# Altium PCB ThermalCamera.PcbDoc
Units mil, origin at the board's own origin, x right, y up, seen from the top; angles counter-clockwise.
Board outline 2150 x 2960 mil, 2 copper layers (Top Layer, Bottom Layer), stack 64.8 mil thick; 71 components, 50 nets, 249 pads, 73 vias.
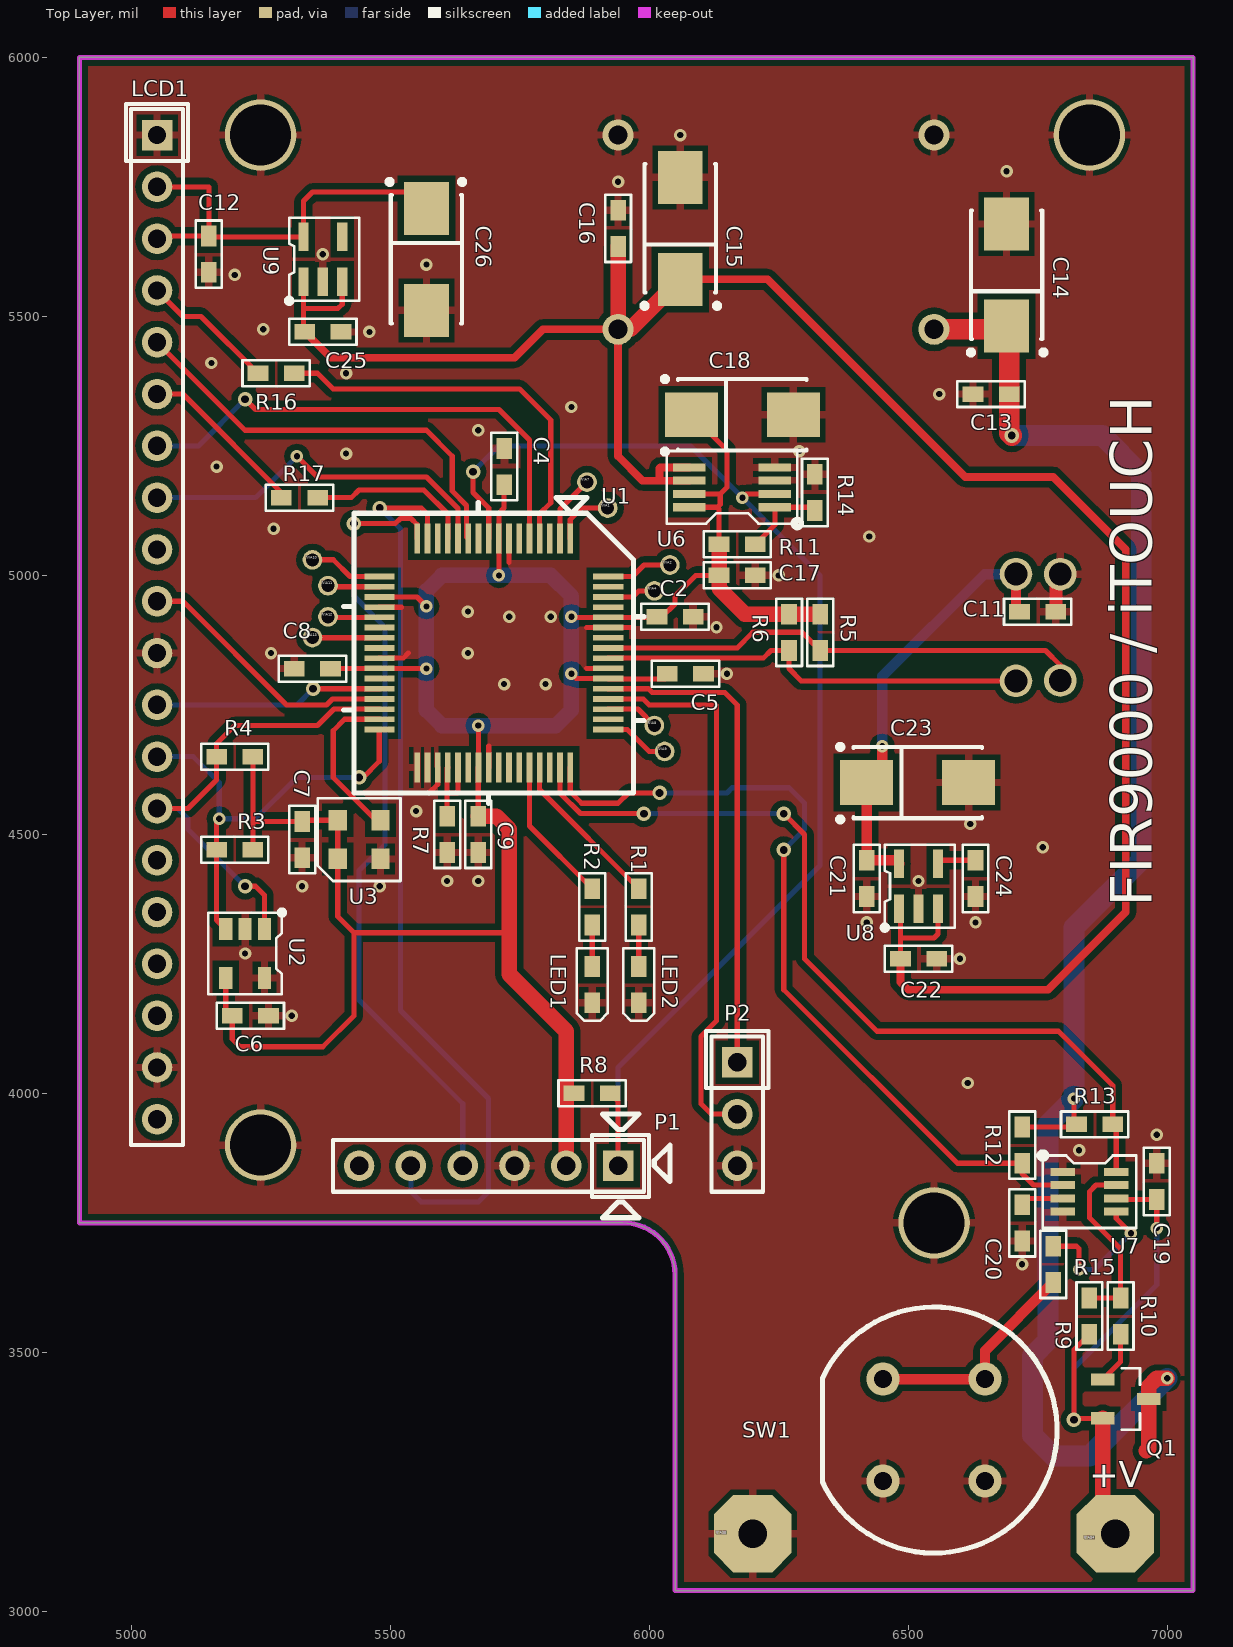
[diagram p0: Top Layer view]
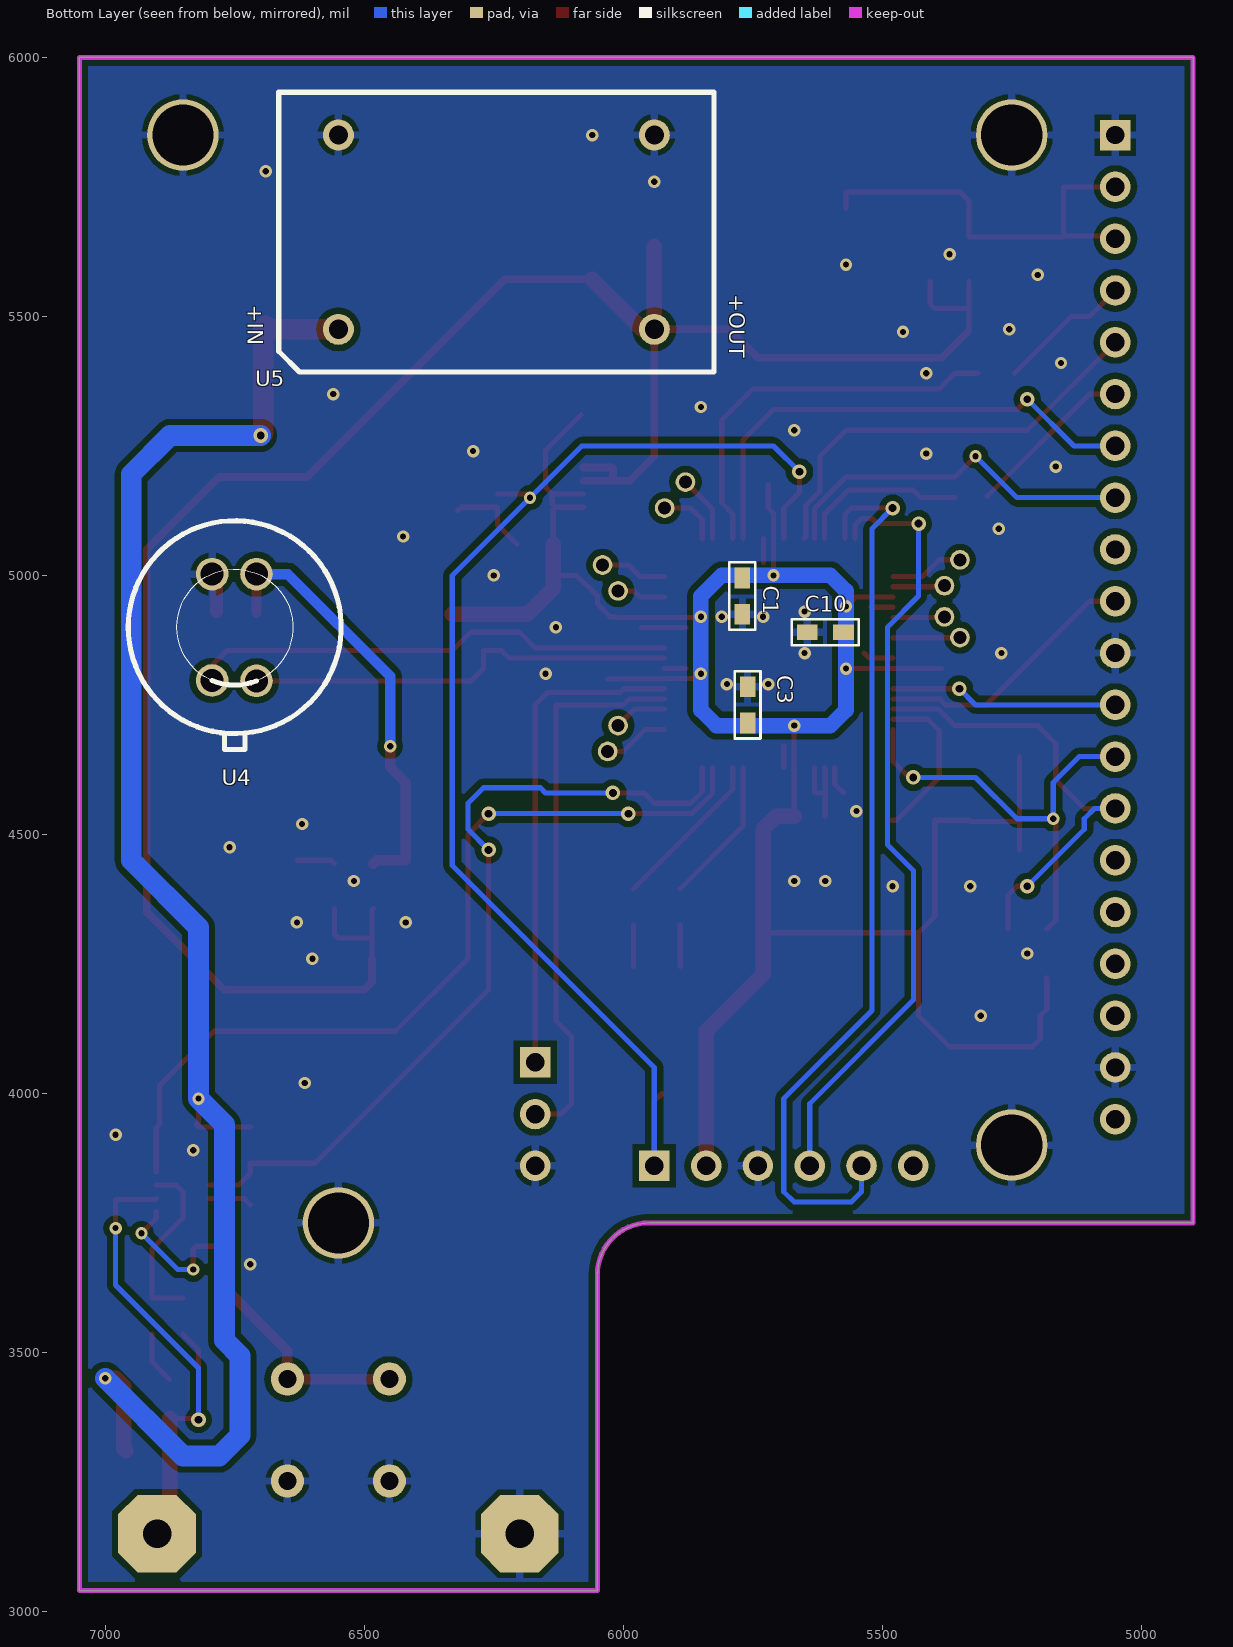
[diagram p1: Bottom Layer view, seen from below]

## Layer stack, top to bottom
Top Solder: solder mask 0.4, Solder Resist, Dk 3.5
Top Layer: signal copper 1.4
Dielectric1: core 62, FR-4, Dk 4.8
Bottom Layer: signal copper 1.4
Bottom Solder: solder mask 0.4, Solder Resist, Dk 3.5

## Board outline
4900,3750 5950,3750 cw(c5950,3650) 6050,3650 6050,3040 7050,3040 7050,6000 4900,6000

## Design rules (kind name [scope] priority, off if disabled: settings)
Clearance "PAD Keepout" [(InPadClass('All Pads')) vs (InPoly)] p1: gap=12 ignorepadtopadclearanceinfootprint=FALSE except(0: Arc-Hole Track-Hole SMDPad-Hole THPad-Hole Via-Hole Fill-Hole Poly-Hole Region-Hole Text-Hole) // 7 Mil Keepout
Clearance "GND Planes" [(inPoly)] p2: gap=12 ignorepadtopadclearanceinfootprint=FALSE except(0: Arc-Hole Track-Hole SMDPad-Hole THPad-Hole Via-Hole Fill-Hole Poly-Hole Region-Hole Text-Hole) // 12 mil Clearence
Clearance [All] p3: gap=6 ignorepadtopadclearanceinfootprint=FALSE except(0: Arc-Hole Track-Hole SMDPad-Hole THPad-Hole Via-Hole Fill-Hole Poly-Hole Region-Hole Text-Hole)
ComponentClearance [All] p1: gap=-1 collisioncheckmode=3 verticalgap=-1 showdistances=FALSE
FanoutControl Fanout_Default [All] p1: bgadir=Out bgaviamode=Centered fanoutstyle=Auto fanoutdirection=OutOnly viagrid=1 // Fanout_Default (Default Rule)
Height [All] p1: minheight=-1 maxheight=1000 prefheight=500
HoleSize [All] p1: absolutevalues=TRUE maxlimit=250 minlimit=8 maxpercent=80.000 minpercent=20.000
HoleToHoleClearance [All] p1: gap=12 allowstackedmicrovias=FALSE
MinimumAnnularRing [All] p1: minimumring=6
MinimumSolderMaskSliver [All] p1: minsoldermaskwidth=1
PlaneClearance [All] p1: clearance=12
PlaneConnect [All] p1: planeconnectstyle=Relief reliefexpansion=12 reliefentries=4 reliefconductorwidth=10 reliefairgap=10
PolygonConnect PolygonConnect_Gnd_Vias [InNet('GND') AND IsVia] p1: connectstyle=Direct reliefconductorwidth=10 reliefentries=4 polygonreliefangle="90 Angle" airgapwidth=10
PolygonConnect PolygonConnect_MTG_Holes [InNet('GND') AND IsVia AND (AsMils(PadXSize_AllLayers) = 250.0)] p2: connectstyle=Direct reliefconductorwidth=10 reliefentries=4 polygonreliefangle="90 Angle" airgapwidth=10
PolygonConnect PolygonConnect_Deafult [All] p3: connectstyle=Relief reliefconductorwidth=15 reliefentries=4 polygonreliefangle="90 Angle" airgapwidth=10
RoutingCorners [All] p1: cornerstyle=45-Degree minsetback=50 maxsetback=100
RoutingVias [All] p1: holewidth=10 width=23 viastyle="Through Hole" minholewidth=8 minwidth=20 maxholewidth=250 maxwidth=300
SilkToSilkClearance [All] p1: silktosilkclearance=0
SilkToSolderMaskClearance SilkscreenOverComponentPads [IsPad] p1: minsilkscreentomaskgap=-1 clearancetoexposedcopper=TRUE
SolderMaskExpansion SolderMaskExpansion_VIAS [IsVia] p1: expansion=-3 istentingtop=FALSE
SolderMaskExpansion SolderMaskExpansion_PADS [IsPad] p2: expansion=3 istentingtop=FALSE
SolderMaskExpansion [All] p3: expansion=3 istentingtop=FALSE
Width [All] p1: maxlimit=200 minlimit=6 preferedwidth=10 minimp=50.000000 maximp=50.000000 favimp=50.000000
15 further rules are at their usual default settings.

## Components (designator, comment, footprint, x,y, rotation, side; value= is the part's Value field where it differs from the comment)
C1 "C603-0.22u" 0603 5770,4960 r270 bottom
C2 "C603-0.01u" 0603 6050,4920 r0 top
C3 "C603-0.22u" 0603 5760,4750 r270 bottom
C4 "C603-0.01u" 0603 5720,5210 r270 top
C5 "C603-0.01u" 0603 6070,4810 r180 top
C6 "C603-0.22u" 0603 5230,4150 r180 top
C7 "C603-0.22u" 0603 5330,4490 r90 top
C8 "C603-0.01u" 0603 5350,4820 r0 top
C9 "C603-0.01u" 0603 5670,4500 r90 top
C10 "C603-0.22u" 0603 5610,4890 r180 bottom
C11 "C603-0.01u" 0603 6750,4930 r0 top
C12 "C603-0.22u" 0603 5150,5620 r90 top
C13 "C603-0.22u" 0603 6660,5350 r180 top
C14 "CT-220u-10V" 6032-28 6690,5580 r90 top
C15 "CT-220u-10V" 6032-28 6060,5670 r90 top
C16 "C603-0.22u" 0603 5940,5670 r90 top
C17 "C603-0.22u" 0603 6170,5000 r0 top
C18 "CT-220u-10V" 6032-28 6180,5310 r0 top
C19 "C603-0.22u" 0603 6980,3830 r90 top
C20 "C603-0.47u" 0603 6720,3750 r270 top
C21 "C603-0.22u" 0603 6420,4415 r270 top
C22 "C603-0.22u" 0603 6520,4260 r0 top
C23 "CT-220u-10V" 6032-28 6518.43,4600 r0 top
C24 "C603-0.22u" 0603 6630,4415 r270 top
C25 "C603-0.22u" 0603 5370,5470 r0 top
C26 "CT-220u-10V" 6032-28 5570,5610 r270 top
LCD1 "Adafruit 2.8\" TFT SPI" Header_SIL_20 5050,5850 r270 top
LED1 "LED603-YEL" 0603LED-YEL 5890,4210 r270 top
LED2 "LED603-YEL" 0603LED-YEL 5980,4210 r270 top
P1 "SIL-6" ProgHeader_SIL 5940,3860 r180 top
P2 "SIL-3" Header_SIL_3 6170,4060 r270 top
Q1 "FDV304P" SOT23 6920,3410 r0 top
R1 "R603-316" 0603 5980,4360 r270 top
R2 "R603-316" 0603 5890,4360 r270 top
R3 "R603-5.11k" 0603 5200,4470 r180 top
R4 "R603-5.11k" 0603 5200,4650 r180 top
R5 "R603-1.54k" 0603 6330,4890 r270 top
R6 "R603-1.54k" 0603 6270,4890 r270 top
R7 "R603-5.11k" 0603 5610,4500 r270 top
R8 "R603-10k" 0603 5890,4000 r0 top
R9 "R603-100k" 0603 6850,3570 r90 top
R10 "R603-100k" 0603 6910,3570 r90 top
R11 "R603-53.6k" 0603 6170,5060 r0 top
R12 "R603-100k" 0603 6720,3900 r270 top
R13 "R603-100k" 0603 6860,3940 r0 top
R14 "R603-30.1k" 0603 6320,5160 r90 top
R15 "R603-1k" 0603 6780,3670 r90 top
R16 "R603-24.9" 0603 5280,5390 r0 top
R17 "R603-24.9" 0603 5325,5150 r0 top
SW1 "D6R40 F1 LFS" D6R40_F1_LFS 6550,3350 r0 top
U1 "PIC32MZ2048EFH064-250I/PT" TQFP64_10x10MC 5700,4850 r270 top
U2 "24LC64FT-I/OT" SOT23_5 5220,4270 r270 top
U3 "DSC6003CI2A-024.0000T" MICREL-3.2x2.5MM-OSC 5440,4490 r90 top
U4 "MLX90640" MLX90640 6750,4900 r180 bottom
U5 "EBAY_MODULE" BUCK_MODULE 6245,5662.5 r0 bottom
U6 "TPS77301DGK" DGK8 6160,5170 r180 top
U7 "LTC2955TS8-2" SOT23_8 6850,3810 r0 top
U8 "LP2985A-3.3DBV" DBV 6520,4400 r90 top
U9 "LP2985A-3.3DBV" DBV 5370,5610 r90 top
VIA1 "VIA038_025" VIA038_25 5920,5130 r90 top
VIA2 "VIA038_025" VIA038_25 6040,5020 r90 top
VIA4 "VIA038_025" VIA038_25 6010,4970 r90 top
VIA7 "VIA038_025" VIA038_25 5880,5180 r90 top
VIA8 "VIA038_025" VIA038_25 6010,4710 r90 top
VIA9 "VIA038_025" VIA038_25 6030,4660 r90 top
VIA10 "VIA038_025" VIA038_25 5350,5030 r90 top
VIA11 "VIA038_025" VIA038_25 5380,4980 r90 top
VIA12 "VIA038_025" VIA038_25 5380,4920 r90 top
VIA13 "VIA038_025" VIA038_25 5350,4880 r90 top
VIA14 "VIA150_055" VIA150_055 6900,3150 r90 top
VIA15 "VIA150_055" VIA150_055 6200,3150 r90 top

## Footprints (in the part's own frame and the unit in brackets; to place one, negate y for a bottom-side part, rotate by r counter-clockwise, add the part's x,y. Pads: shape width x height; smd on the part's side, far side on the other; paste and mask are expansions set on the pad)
0603 [mil] "0603 Normal Pads"
  rect 40x30 smd: 1(-35,0) 2(35,0)
  silkscreen extent -65,-25 65,25, body extent -36,-16 36,16, height 38
0603LED-YEL [mil] "0603 LED YELLOW"
  rect 40x30 smd: 1(35,0) 2(-35,0)
  silkscreen extent -70,-30 70,30, body extent -35,-15 35,15, height 31
6032-28 [mm] "Tantalum C"
  rect 2.6x2.2 smd: 1(-2.5,0) 2(2.5,0)
  silkscreen extent -3.92,-1.93 3.15,1.87, body extent -2.57,-1.4 2.57,1.4, height 2.49
BUCK_MODULE [mil] "EBAY BUCK CONVERTER MODULE"
  round 60 hole 37: 1(305,187.5) 2(305,-187.5) 3(-305,-187.5) 4(-305,187.5)
  silkscreen extent -420,-270 420,270, body extent -400,-250 400,250, height 200
D6R40_F1_LFS [mil] "TH PUSH BUTTON TACTILE VERT"
  round 64 hole 35: 1(-98.43,98.43) 2(-98.43,-98.43) 3(98.43,-98.43) 4(98.43,98.43)
  silkscreen extent -215,-238 237,238, body extent -234,-236 236,236, height 571
DBV [mil] "TI DBV FOOTPRINT (SOT-23-5)"
  rect 55.1x19.7 smd: 1(-43.3,37.4) 2(-43.3,0) 3(-43.3,-37.4) 4(43.3,-37.4) 5(43.3,37.4)
  silkscreen extent -85,-70 80,70, body extent -56,-58 56,57, height 42
DGK8 [mil] "MSOP8 (TI)"
  rect 63x15.7 smd: 1(-82.7,38.4) 2(-82.7,12.8) 3(-82.7,-12.8) 4(-82.7,-38.4) 5(82.7,-38.4) 6(82.7,-12.8) 7(82.7,12.8) 8(82.7,38.4)
  silkscreen extent -134,-70 126,78, body extent -96,-59 97,59, height 38
Header_SIL_3 [mm] "3 Pin Header (SIL)"
  rect 1.5x1.5 hole 0.9: 1(0,0)
  round 1.5 hole 0.9: 2(2.54,0) 3(5.08,0)
  silkscreen extent -1.52,-1.52 6.35,1.52, body extent -1.27,-1.27 6.35,1.27, height 5.79
Header_SIL_20 [mm] "20 Pin Header (SIL)"
  rect 1.5x1.5 hole 0.9: 1(0,0)
  round 1.5 hole 0.9: 2(2.54,0) 3(5.08,0) 4(7.62,0) 5(10.16,0) 6(12.7,0) 7(15.24,0) 8(17.78,0) 9(20.32,0) 10(22.86,0) 11(25.4,0) 12(27.94,0) 13(30.48,0) 14(33.02,0) 15(35.56,0) 16(38.1,0) 17(40.64,0) 18(43.18,0) 19(45.72,0) 20(48.26,0)
  silkscreen extent -1.52,-1.52 49.53,1.52, body extent -1.27,-1.27 49.53,1.28, height 5.79
MICREL-3.2x2.5MM-OSC [mm] "MICREL 3.2X2.5MM A PKG OSCILATOR"
  rect 1x0.9 smd: 1(-0.95,1.05) 2(-0.95,-1.05) 3(0.95,-1.05) 4(0.95,1.05)
  silkscreen extent -2.03,-2.03 2.03,2.03, body extent -1.26,-1.61 1.26,1.61, height 0.91
MLX90640 [mm] "IR SENSOR"
  round 1.6 hole 1.12: 1(-1.11,-2.614) 2(1.064,-2.633) 3(1.064,2.6) 4(-1.11,2.6)
  silkscreen extent -5.22,-6 5.22,5.22, body extent -4.61,-5.25 4.65,4.64, height 11.35
ProgHeader_SIL [mm] "6 Pin Programming Header (SIL)"
  rect 1.5x1.5 hole 0.9: 1(0,0)
  round 1.5 hole 0.9: 2(2.54,0) 3(5.08,0) 4(7.62,0) 5(10.16,0) 6(12.7,0)
  silkscreen extent -2.54,-2.54 13.97,2.54, body extent -1.27,-1.27 13.97,1.28, height 5.79
SOT23 [mm] "SOT23, 123 Normal Pinout"
  rect 1.15x0.6 smd: 1(-1.125,0.95) 2(1.125,0) 3(-1.125,-0.95)
  silkscreen extent -0.2,-1.5 0.7,1.5, body extent -1.26,-1.46 1.26,1.46, height 0.97
SOT23_5 [mm] "SOT23, 5 Lead Normal Pinout"
  rect 1.1x0.65 smd: 1(-1.2,0.95) 2(-1.2,0) 3(-1.2,-0.95) 4(1.2,-0.95) 5(1.2,0.95)
  silkscreen extent -2.13,-1.8 2,1.93, body extent -1.42,-1.46 1.42,1.46, height 1.07
SOT23_8 [mil] "TSOT23-8 From LTC6910 Data Sheet"
  rect 48x15.7 smd: 1(-51.6,38.4) 2(-51.6,12.8) 3(-51.6,-12.8) 4(-51.6,-38.4) 5(51.6,-38.4) 6(51.6,-12.8) 7(51.6,12.8) 8(51.6,38.4)
  silkscreen extent -97,-70 90,77, body extent -55,-57 55,57, height 39
TQFP64_10x10MC [mil] "TQFP64 10x10x1.6mm 0.5mm grid"
  rect 58x11 smd: 1(-221,147.64) 2(-221,127.95) 3(-221,108.27) 4(-221,88.58) 5(-221,68.9) 6(-221,49.21) 7(-221,29.53) 8(-221,9.84) 9(-221,-9.84) 10(-221,-29.53) 11(-221,-49.21) 12(-221,-68.9) 13(-221,-88.58) 14(-221,-108.27) 15(-221,-127.95) 16(-221,-147.64) 33(221,-147.64) 34(221,-127.95) 35(221,-108.27) 36(221,-88.58) 37(221,-68.9) 38(221,-49.21) 39(221,-29.53) 40(221,-9.84) 41(221,9.84) 42(221,29.53) 43(221,49.21) 44(221,68.9) 45(221,88.58) 46(221,108.27) 47(221,127.95) 48(221,147.64)
  rect 11x58 smd: 17(-147.64,-221) 18(-127.95,-221) 19(-108.27,-221) 20(-88.58,-221) 21(-68.9,-221) 22(-49.21,-221) 23(-29.53,-221) 24(-9.84,-221) 25(9.84,-221) 26(29.53,-221) 27(49.21,-221) 28(68.9,-221) 29(88.58,-221) 30(108.27,-221) 31(127.95,-221) 32(147.64,-221) 49(147.64,221) 50(127.95,221) 51(108.27,221) 52(88.58,221) 53(68.9,221) 54(49.21,221) 55(29.53,221) 56(9.84,221) 57(-9.84,221) 58(-29.53,221) 59(-49.21,221) 60(-68.9,221) 61(-88.58,221) 62(-108.27,221) 63(-127.95,221) 64(-147.64,221)
  silkscreen extent -300,-290 290,290, body extent -236,-236 236,236, height 47
VIA038_25 [mil] "25/38 Mil PCB Via"
  round 38 hole 25: 1(0,0)
VIA150_055 [mil] "150/55 Mil PCB Via"
  oct 150x150 hole 55: 1(0,0)

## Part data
C1 C2 C3 C4 C5 C6 C7 C8 C9 C10 C11 C12 C13 C16 C17 C19 C20 C21 C22 C24 C25: library part C0603-0.22u, "0.22uF 50V X7R 603 Capacitor"
C14 C15 C18 C23 C26: "220uF/10V Tant"
LCD1: "240x320 TFT LCD"
LED1 LED2: "Yellow LED"
P1: library part "Prog PICKIT Header (SIL)", "PICKIT Programming Header (SIL)"
P2: library part Header_SIL_3, "Header SIL 3 Pin"
Q1: "PMOS 25V, 1.1 Ohm, 460mA"
R1 R2 R3 R4 R5 R6 R7 R8 R9 R10 R11 R12 R13 R14 R15 R16 R17: library part R0603, "0603 Resistor"
SW1: library part PB-PANEL_1, "PB TACTILE THROUGH HOLE"
U1: "PIC32MZ 250 MHz TQFP"
U2: "64K I2C EEPROM"
U3: library part "MEMS 24MHz", "24MHz CLOCK 1.8-3.3V Low Power"
U4: "IR SENSOR 55 DEGREE"
U5: library part EBAY_BUCK_MODULE, "EBAY BUCK MODULE"
U6: "250mA LDO W/Reset Output"
U7: "PushButton Controller"
U8 U9: library part LP2985A, "150mA LDO W/ENABLE"
VIA1 VIA2 VIA4 VIA7 VIA8 VIA9 VIA10 VIA11 VIA12 VIA13: "38/25 Via Only"
VIA14 VIA15: "150 / 55 Via Only"

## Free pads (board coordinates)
  round 138 hole 118: 2(6550,3750) 3(5250,5850) 4(6850,5850) 5(5250,3900)

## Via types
v1: diameter 24, hole 12, Top Layer to Bottom Layer, 60 vias
v2: diameter 28, hole 15, Top Layer to Bottom Layer, 13 vias

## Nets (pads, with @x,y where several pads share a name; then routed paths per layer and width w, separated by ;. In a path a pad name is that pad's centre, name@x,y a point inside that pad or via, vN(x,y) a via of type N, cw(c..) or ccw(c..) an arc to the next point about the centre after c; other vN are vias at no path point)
+3.3V_DIG: C1.1 C2.1 C3.2 C4.2 C5.2 C6.2 C7.2 C8.2 C9.2 C10.2 C17.1 C18.1 P1.2 R3.1 R4.1 R5.1 R6.1 R8.1 R11.1 U1.8 U1.19 U1.26 U1.39 U1.54 U1.60 U2.4 U3.1 U3.4 U6.7 U6.8 | length 5106.6
  Top Layer w10: U2.4 5182.6,4162.4 C6.2 5195,4105 5210,4090 5370,4090 5430,4150 5430,4310 ; R3.1 5235,4525 ; R4.1 5235,4525 ; C8.2 5385.47,4820.47 U1.26 5569.53,4820.47 v1(5570,4820) ; U1.19 5551.73,4958.27 v1(5570,4940) ; C9.2 5670,4628.53 U1.39 5670.47,4709.53 v1(5670,4710) ; v1(5710,5000) 5709.84,5000.16 U1.8 5709.84,5119.84 5720,5130 C4.2 ; 5730,4310 5430,4310 ; v1(5850,4810) 5859.21,4800.79 U1.54 5921.79,4800 C5.2@6030,4800 ; v1(5850,4920) 5851.1,4918.9 U1.60 6013.9,4918.9 C2.1 6025,4920 6050,4945 6050,4960 6090,5000 C17.1 ; U6.8 6131.6,5131.6 ; U6.7 6137.2,5157.2 ; C18.1 6150,5241.57 6150,5170 6137.2,5157.2 ; R11.1 6135,5128.2 6131.6,5131.6 ; 5235,4525 C7.2 5332.4,4527.4 U3.4 U3.1 5398.66,4341.34 5430,4310 ; 6131.6,5131.6 6137.2,5137.2 6137.2,5157.2
  Top Layer w30: C9.2 5705,4535 5730,4510 5730,4310 5730,4230 5840,4120 P1.2 ; R11.1 C17.1 6135,4975 6185,4925 R6.1 R5.1
  Bottom Layer w30: 5570,4740 v1(5570,4820) v1(5570,4940) 5570,4970 5600,5000 v1(5710,5000) 5810,5000 5850,4960 v1(5850,4920) v1(5850,4810) 5850,4740 5820,4710 v1(5670,4710) 5600,4710 5570,4740
+3.3V_LCD: C12.2 C26.1 LCD1.2 LCD1.3 U9.5 | length 825.9
  Top Layer w10: LCD1.3 5055,5655 C12.2 ; LCD1.2 5150,5750 C12.2 ; C26.1 5570,5740 5350,5740 5332.6,5722.6 U9.5 5151.7,5653.3 C12.2
+3.3V_SENSOR: C11.1 C21.1 C23.1 U4.3 U8.5 | length 846.9
  Top Layer w20: v1(6450,4670) 6450,4630 C23.1 C21.1 6475.9,4450 U8.5 ; C11.1@6708.11,4928.11 U4.3
  Bottom Layer w20: v1(6450,4670) 6450,4805 6647.36,5002.36 U4.3
+3.5V_REG: C15.1 C16.1 C22.1 C25.1 U5.4 U6.5 U6.6 U8.1 U8.3 U9.1 U9.3 | length 4217.4
  Top Layer w10: C25.1@5332.6,5470 5332.6,5515 ; U9.1 5332.6,5515 ; U9.3 5407.4,5523.4 5399,5515 5332.6,5515 ; U8.1 6485,4354.3 6485,4300 ; C22.1 6485,4300 ; U8.3 6557.4,4307.4 6550,4300 6485,4300
  Top Layer w15: C25.1 5385,5420 5740,5420 5795,5475 U5.4 5940,5230 5987.2,5182.8 6020,5182.8 ; C15.1 6228.43,5571.57 6610,5190 6780,5190 6920,5050 6920,4350 6770,4200 6500,4200 6485,4215 C22.1 ; U6.6 6020,5182.8 ; U6.5 6021.6,5208.4 6020,5206.8 6020,5182.8
  Top Layer w30: C16.1 U5.4 5963.43,5475 C15.1
GND: C1.2 C2.2 C3.1 C4.1 C5.1 C6.1 C7.1 C8.1 C9.1 C10.1 C11.2 C12.1 C13.2 C14.2 C15.2 C16.2 C17.2 C18.2 C19.2 C20.2 C21.2 C22.2 C23.2 C24.2 C25.2 C26.2 LCD1.1 LCD1.11 LCD1.19 LED1.1 LED2.1 P1.3 P2.3 pad.2 pad.3 pad.4 pad.5 R7.2 R14.2 SW1.2 SW1.3 U1.7 U1.20 U1.25 U1.33 U1.34 U1.35 U1.40 U1.55 U1.59 U2.2 U2.5 U3.2 U4.4 U5.2 U5.3 U6.3 U6.4 U7.1 U7.4 U8.2 U9.2 VIA15.1 | length 449.1
  Top Layer w10: U1.25 5525.16,4840.16 5535,4850 ; U1.20 5521.42,4938.58 ; 5575,4580 5591.73,4596.73 U1.35 ; U1.40 5690.16,4670.16 ; 5729.53,5025.47 U1.7 ; 5879.21,4899.21 U1.59 5965.79,4899.21 ; 5879.53,4820.47 U1.55
  Top Layer w15: U4.4@6785,4993.67 U4.4
  Top Layer w25: C11.2 U4.4@6785,4993.67
  other v1: 6720,3670 6830,3890 6980,3920 6615,4020 5310,4150 6600,4260 5220,4270 6420,4330 6630,4330 5330,4400 5480,4400 5610,4410 5670,4410 6520,4410 6760,4475 6620,4520 5550,4545 5720,4790 5800,4790 6150,4810 5270,4850 5650,4850 6130,4900 5730,4920 5810,4920 5650,4930 6250,5000 6425,5075 5275,5090 5165,5210 5415,5235 6290,5240 5670,5280 5850,5325 6560,5350 5415,5390 5155,5410 5460,5470 5255,5475 5200,5580 5570,5600 5370,5620 5940,5760 6690,5780 6060,5850
NetC13_1: C13.1 C14.1 Q1.2 R12.1 R13.1 U5.1 | length 3275.9
  Top Layer w10: R12.1 6820,3935 R13.1 6820,3945 v1(6820,3990)
  Top Layer w30: 6960,3310 6964.29,3314.29 Q1.2 6964.29,3434.29 6980,3450 v1(7000,3450)
  Top Layer w40: U5.1 6683.43,5475 C14.1 6695,5476.57 C13.1 6695,5275 v2(6700,5270)
  Bottom Layer w40: v2(6700,5270) 6875,5270 ; 6895,5250 6875,5270 ; v1(7000,3450) 6850,3300 6780,3300 6740,3340 6740,3493.23 6770,3523.23 6770,3940 v1(6820,3990) 6820,4320 6950,4450 6950,5195 6875,5270
NetC19_1: C19.1 Q1.3 R9.1 U7.6 VIA14.1 | length 1037.5
  Top Layer w10: R9.1 6820,3505 v2(6820,3370) 6822.6,3372.6 Q1.3 ; U7.6 6903.8,3795 C19.1 v1(6980,3740)
  Top Layer w30: Q1.3 6875.71,3174.29 VIA14.1
  Bottom Layer w10: v2(6820,3370) 6820,3470 6980,3630 v1(6980,3740)
NetC20_1: C20.1 U7.3 | length 83.5
  Top Layer w10: C20.1 6732.2,3797.2 U7.3
NetC24_1: C24.1 U8.4 | length 75.4
  Top Layer w10: U8.4 6564.1,4450 C24.1
NetLCD1_4: LCD1.4 R16.1 | length 261.3
  Top Layer w10: LCD1.4 5100,5500 5135,5500 R16.1
NetLCD1_5: LCD1.5 U1.11 | length 832.9
  Top Layer w10: LCD1.5 5220,5280 5570,5280 5620,5230 5620,5162.63 5647.6,5135.02 5647.6,5074.19 U1.11
NetLCD1_6: LCD1.6 R17.1 | length 329
  Top Layer w10: LCD1.6 5100,5350 R17.1@5297.25,5152.75
NetLCD1_7: LCD1.7 U1.5 | length 979
  Top Layer w10: v2(5220,5340) 5240,5320 5710,5320 5768.9,5261.1 U1.5
  Bottom Layer w10: LCD1.7 5130,5250 v2(5220,5340)
NetLCD1_8: LCD1.8 U1.12 | length 714
  Top Layer w10: v1(5320,5230) 5360,5190 5570,5190 5631.1,5128.9 U1.12
  Bottom Layer w10: LCD1.8 5240,5150 v1(5320,5230)
NetLCD1_10: LCD1.10 U1.29 | length 516.6
  Top Layer w10: LCD1.10 5100,4950 5300,4750 5377.37,4750 5388.79,4761.42 U1.29
NetLCD1_12: LCD1.12 U1.28 | length 441.9
  Top Layer w10: v2(5351.1,4781.1) U1.28
  Bottom Layer w10: LCD1.12 5320,4750 v2(5351.1,4781.1)
NetLCD1_13: LCD1.13 R3.2 U1.32 U2.3 | length 849.2
  Top Layer w10: v1(5170,4530) 5165,4525 R3.2 5165,4334.84 U2.3 ; v2(5440,4610) 5448,4610 5479,4641 U1.32
  Bottom Layer w10: LCD1.13 5120,4650 5170,4600 v1(5170,4530) 5240,4530 5320,4610 v2(5440,4610)
NetLCD1_14: LCD1.14 R4.2 U1.30 U2.1 | length 903.2
  Top Layer w10: LCD1.14 5110,4550 5165,4605 R4.2 5165,4675 5200,4710 5360,4710 5391.73,4741.73 U1.30 ; v2(5220,4400) 5240,4400 5257.4,4382.6 U2.1
  Bottom Layer w10: LCD1.14 5090,4550 5110,4530 5110,4510 v2(5220,4400)
NetLED1_2: LED1.2 R2.2 | length 80
  Top Layer w10: LED1.2 R2.2
NetLED2_2: LED2.2 R1.2 | length 80
  Top Layer w10: LED2.2 R1.2
NetP1_1: P1.1 R8.2 U1.9 U6.2 | length 2449.2
  Top Layer w10: v2(5660,5200) 5660,5160 5690.16,5129.84 U1.9 ; R8.2 5940,3985 P1.1 ; v1(6180,5150) 6187.2,5157.2 U6.2
  Bottom Layer w10: v2(5660,5200) 5710,5250 6080,5250 v1(6180,5150) 6330,5000 6330,4440 5940,4050 P1.1
NetP1_4: P1.4 U1.16 | length 1526.7
  Top Layer w10: v2(5430,5100) 5510,5100 5520,5110 5540,5110 5552.36,5097.64 U1.16
  Bottom Layer w10: v2(5430,5100) 5430,4960 5490,4900 5490,4480 5440,4430 5440,4180 5640,3980 P1.4
NetP1_5: P1.5 U1.15 | length 1767.5
  Top Layer w10: v2(5480,5130) 5560,5130 5572.05,5117.95 U1.15
  Bottom Layer w10: v2(5480,5130) 5520,5090 5520,4160 5690,3990 5690,3810 5670,3790 5560,3790 5540,3810 P1.5
NetP2_1: P2.1 U1.53 | length 951.9
  Top Layer w10: U1.53 5998.9,4781.1 6006,4774 6146,4774 6170,4750 P2.1
NetP2_2: P2.2 U1.52 | length 1074.4
  Top Layer w10: U1.52 5988.58,4761.42 6000,4750 6130,4750 6130,4140 6100,4110 6100,3980 6120,3960 P2.2
NetQ1_1: Q1.1 R10.1 | length 101.8
  Top Layer w10: Q1.1 6910,3481.69 R10.1
NetR1_1: R1.1 U1.45 | length 313.3
  Top Layer w10: U1.45 5788.58,4586.42 R1.1
NetR2_1: R2.1 U1.44 | length 284.2
  Top Layer w10: U1.44 5768.9,4516.1 R2.1
NetR5_2: R5.2 U1.57 U4.1 | length 940.8
  Top Layer w10: U1.57 5921.16,4860 6170,4860 6200,4890 6295,4890 R5.2 6765,4855 6793.69,4826.31 U4.1
NetR6_2: R6.2 U1.56 U4.2 | length 838.1
  Top Layer w10: U1.56 6220.16,4840.16 6235,4855 R6.2 6270,4820 6293.67,4796.33 U4.2
NetR7_1: R7.1 U1.36 U1.37 | length 164
  Top Layer w10: R7.1 5610,4580 ; U1.36 5610,4627.58 5610,4580 ; U1.37 5631.1,4581.1 5630,4580 5610,4580
NetR9_2: R9.2 R10.2 U7.7 | length 346.8
  Top Layer w10: R9.2 R10.2 6910,3700 6850,3760 6850,3810 6862.8,3822.8 U7.7
NetR11_2: R11.2 R14.1 U6.1 | length 167.2
  Top Layer w10: R11.2 6242.7,5097.7 U6.1 6313.4,5131.6 R14.1
NetR12_2: R12.2 U1.48 U7.2 | length 1616
  Top Layer w10: U1.48 5847.64,4582.36 5870,4560 5940,4560 5960,4580 v2(6020,4580) ; v2(6260,4470) 6260,4200 6595,3865 R12.2 6720,3845 6742.2,3822.8 U7.2
  Bottom Layer w10: v2(6020,4580) 6150,4580 6160,4590 6270,4590 6300,4560 6300,4510 v2(6260,4470)
NetR13_2: R13.2 U1.47 U7.8 | length 1660.3
  Top Layer w10: U1.47 5827.95,4579.42 5867.37,4540 v2(5990,4540) ; v2(6260,4540) 6300,4500 6300,4260 6440,4120 6790,4120 6895,4015 R13.2 6901.6,3933.4 U7.8
  Bottom Layer w10: v2(5990,4540) v2(6260,4540)
NetR15_1: R15.1 SW1.1 SW1.4 | length 437.9
  Top Layer w20: SW1.1 SW1.4 6648.43,3503.43 R15.1
NetR15_2: R15.2 U7.5 | length 274.4
  Top Layer w10: R15.2 6825,3705 6830,3700 v1(6830,3660) ; U7.5 6901.6,3758.4 v1(6930,3730)
  Bottom Layer w10: v1(6830,3660) 6860,3660 v1(6930,3730)
NetR16_2: R16.2 U1.4 | length 770.2
  Top Layer w10: R16.2 5360,5390 5390,5360 5750,5360 5810,5300 5810,5140 5788.58,5118.58 U1.4
NetR17_2: R17.2 U1.13 | length 324.4
  Top Layer w10: R17.2 5425,5150 5440,5165 5565,5165 5611.42,5118.58 U1.13
NetU1_1: U1.1 VIA1.1 | length 118.3
  Top Layer w10: U1.1 5847.64,5107.64 5870,5130 VIA1.1
NetU1_2: U1.2 VIA7.1 | length 130.6
  Top Layer w10: U1.2 5827.95,5127.95 VIA7.1
NetU1_17: U1.17 VIA10.1 | length 142.4
  Top Layer w10: VIA10.1 5390,5030 5422.36,4997.64 U1.17
NetU1_18: U1.18 VIA11.1 | length 99.8
  Top Layer w10: VIA11.1 5382.05,4977.95 U1.18
NetU1_21: U1.21 VIA12.1 | length 99.5
  Top Layer w10: VIA12.1 5381.1,4918.9 U1.21
NetU1_23: U1.23 VIA13.1 | length 129.2
  Top Layer w10: VIA13.1 5350.47,4879.53 U1.23
NetU1_31: U1.31 U3.3 | length 313.7
  Top Layer w10: U1.31 5412.05,4722.05 5390,4700 5390,4610 5472.6,4527.4 U3.3
NetU1_49: U1.49 VIA9.1 | length 126.5
  Top Layer w10: U1.49 5957.64,4702.36 6000,4660 VIA9.1
NetU1_51: U1.51 VIA8.1 | length 102.1
  Top Layer w10: U1.51 5978.27,4741.73 VIA8.1
NetU1_62: U1.62 VIA4.1 | length 93.9
  Top Layer w10: U1.62 5968.27,4958.27 5980,4970 VIA4.1
NetU1_64: U1.64 VIA2.1 | length 128.3
  Top Layer w10: U1.64 5967.64,4997.64 5990,5020 VIA2.1
pads on no net: LCD1.9 LCD1.15 LCD1.16 LCD1.17 LCD1.18 LCD1.20 P1.6 U1.3 U1.6 U1.10 U1.14 U1.22 U1.24 U1.27 U1.38 U1.41 U1.42 U1.43 U1.46 U1.50 U1.58 U1.61 U1.63 U9.4

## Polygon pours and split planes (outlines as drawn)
GND on Bottom Layer "BG" (solid, remove dead copper, pour order 4): 4750,6100 7250,6100 7250,2850 4750,2850
GND on Top Layer "TG" (solid, remove dead copper, pour order 2): 4700,6100 7250,6100 7250,2850 4700,2850

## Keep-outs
Keep-Out Layer:
  the board outline again, w10

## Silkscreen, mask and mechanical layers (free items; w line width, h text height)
Top Overlay:
  text "FIR9000 / iTOUCH" at 6970,4360 h80 r90
  text "+V" at 6850,3240 h50
PCB_Outline_1:
  the board outline again, w10
Assy_Top_3:
  text "ASSY TOP" at 14320,550 h200
Assy_Bot_4:
  text "ASSY BOT" at 15730,560 h200
Drawing_Sheet_16:
  lines w1: 13803,500 16803,500 ; 13803,800 16803,800 ; 200,200 16800,200 16800,10800 200,10800 200,200
  lines w5: 13803,209 13803,809 13803,1409 16803,1409 16803,209 ; 15903,209 15903,809
  lines w10: 0,-11 9997,-11
  text "TITLE:" at 13853,709 h45
  text "REV:" at 15953,709 h45
  text ".PRINT_DATE" at 15960,520 h50
  text "DWG NO:" at 13853,409 h45
  text "DIMENSIONS IN MILS" at 16054,328 h45
Drill Drawing:
  text ".LEGEND" at 600,700 h70
  text "FAB DOC" at 14320,550 h200
Construction_Lines_17:
  lines w10: 6000,4000 9000,6000 ; 6000,6000 9000,4000

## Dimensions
7050,6065 to 4900,6040 on PCB_Outline_1
4835,6000 to 5975,3040 on PCB_Outline_1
